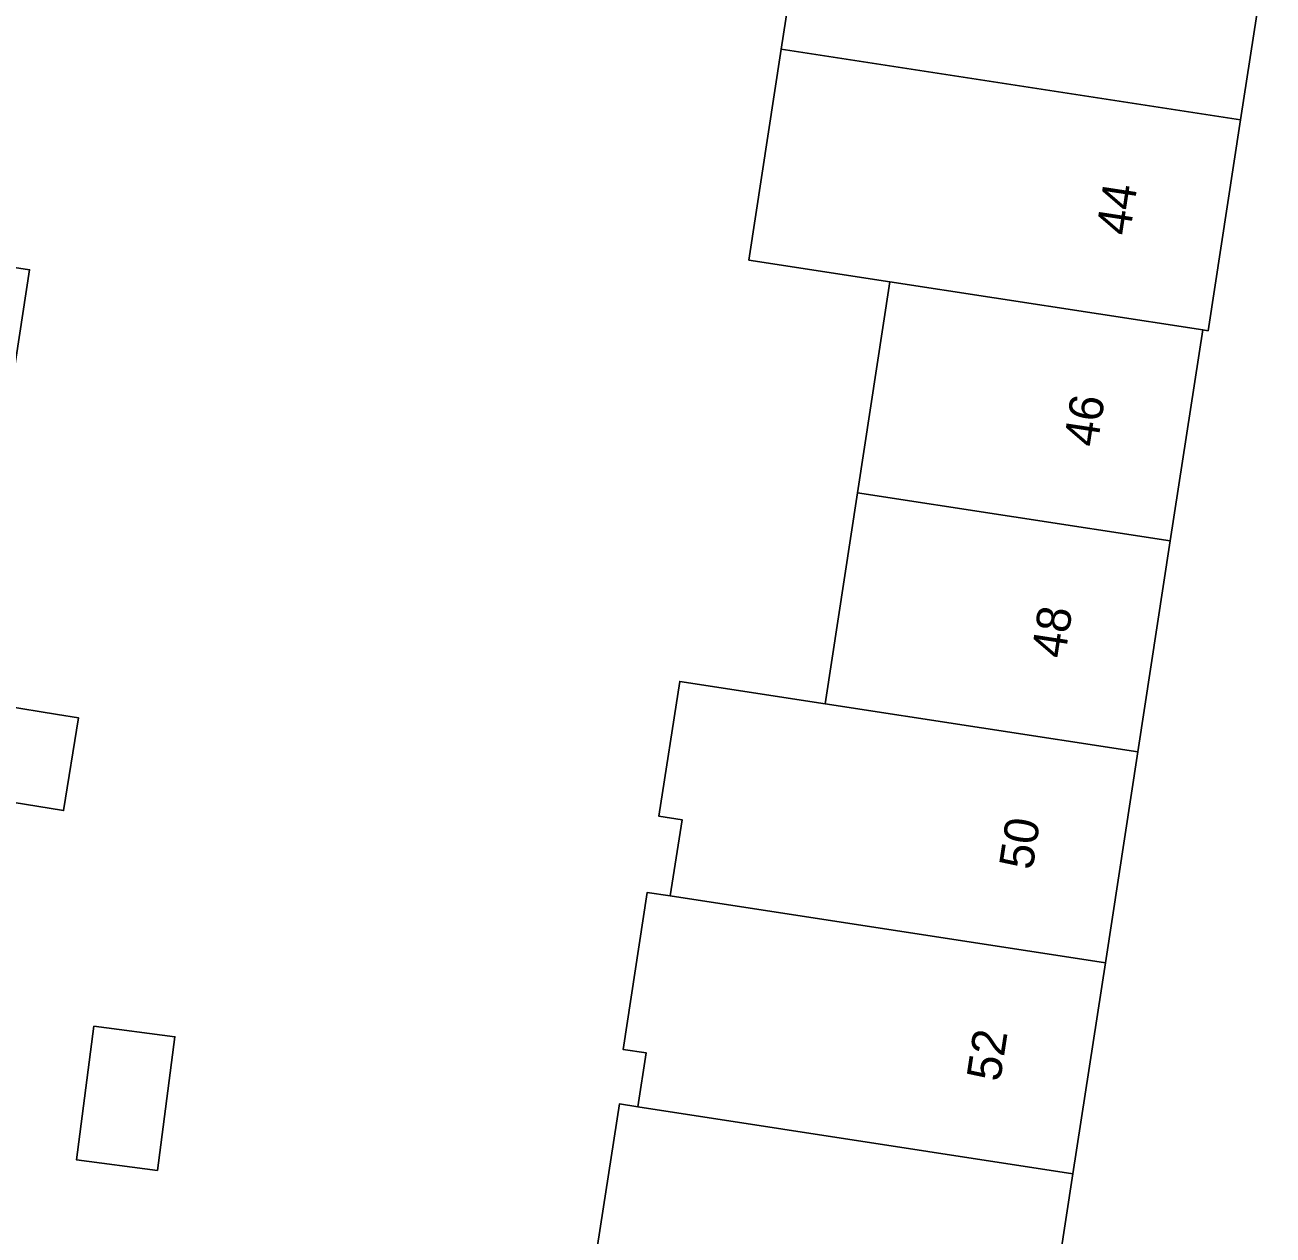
# Model space of a CAD drawing. Extents: x 161483 to 162250, y 379484 to 380833.
# Drawn here: x 162068.29 to 162104.92, y 380548.53 to 380584.05 of the extents above; entities that cross this region are included whole.
import ezdxf

# ---------------------------------------------------------------- set-up
doc = ezdxf.new("R2010")
doc.units = 0
for name, color, linetype in [('IMGEO_Erf', 7, 'Continuous'), ('IMGEO_Pand', 7, 'Continuous'), ('IMGEO_Pand_nummerreeks', 7, 'Continuous')]:
    doc.layers.add(name, color=color, linetype=linetype)

msp = doc.modelspace()

# ---------------------------------------------------------------- linework, layer by layer
at = {"layer": 'IMGEO_Erf'}
for points in [[(162104.903, 380587.33), (162103.971, 380581.267), (162103.018, 380575.074), (162102.86, 380575.098), (162101.908, 380568.906), (162100.956, 380562.714), (162100.003, 380556.522), (162099.051, 380550.33), (162098.099, 380544.138), (162097.119, 380537.766), (162083.147, 380539.987), (162082.606, 380536.471), (162081.595, 380528.392), (162091.517, 380526.858), (162101.213, 380525.474)], [(162093.677, 380576.511), (162089.537, 380577.148), (162090.489, 380583.341), (162091.032, 380586.872)], [(162085.098, 380548.228), (162085.736, 380552.379), (162086.279, 380552.295), (162086.523, 380553.879), (162085.846, 380553.983), (162086.555, 380558.591), (162087.231, 380558.487), (162087.575, 380560.721), (162086.898, 380560.825), (162087.507, 380564.783), (162091.772, 380564.127), (162092.724, 380570.319), (162093.677, 380576.511)], [(162067.691, 380564.063), (162069.245, 380563.811), (162069.863, 380563.711), (162069.423, 380560.992), (162064.586, 380561.774)]]:
    msp.add_lwpolyline(points, dxfattribs=at)
for points in [[(162067.637, 380571.741), (162062.833, 380572.48), (162063.227, 380575.041), (162063.622, 380577.602), (162068.425, 380576.862), (162068.031, 380574.302)], [(162070.314, 380554.665), (162072.69, 380554.352), (162072.174, 380550.429), (162069.797, 380550.741)]]:
    msp.add_lwpolyline(points, close=True, dxfattribs=at)
at = {"layer": 'IMGEO_Pand'}
for points in [[(162104.903, 380587.33), (162104.923, 380587.459), (162104.721, 380587.49), (162095.581, 380588.896), (162091.962, 380589.453), (162091.552, 380586.792), (162091.032, 380586.872), (162090.489, 380583.341), (162103.971, 380581.267)], [(162103.971, 380581.267), (162090.489, 380583.341), (162089.537, 380577.148), (162093.677, 380576.511), (162102.86, 380575.098), (162103.018, 380575.074)], [(162063.227, 380575.041), (162068.031, 380574.302), (162068.425, 380576.862), (162063.622, 380577.602)], [(162102.86, 380575.098), (162093.677, 380576.511), (162092.724, 380570.319), (162101.908, 380568.906)], [(162091.772, 380564.127), (162100.956, 380562.714), (162101.908, 380568.906), (162092.724, 380570.319)], [(162067.691, 380564.063), (162061.586, 380565.051), (162061.226, 380562.823), (162061.146, 380562.33), (162064.586, 380561.774), (162069.423, 380560.992), (162069.863, 380563.711), (162069.245, 380563.811)], [(162091.772, 380564.127), (162087.507, 380564.783), (162086.898, 380560.825), (162087.575, 380560.721), (162087.231, 380558.487), (162100.003, 380556.522), (162100.956, 380562.714)], [(162087.231, 380558.487), (162086.555, 380558.591), (162085.846, 380553.983), (162086.523, 380553.879), (162086.279, 380552.295), (162099.051, 380550.33), (162100.003, 380556.522)], [(162070.314, 380554.665), (162069.797, 380550.741), (162072.174, 380550.429), (162072.69, 380554.352)], [(162086.279, 380552.295), (162085.736, 380552.379), (162085.098, 380548.228), (162086.976, 380547.94), (162086.662, 380545.896), (162088.915, 380545.55), (162098.099, 380544.138), (162099.051, 380550.33)]]:
    msp.add_lwpolyline(points, close=True, dxfattribs=at)

# ---------------------------------------------------------------- texts
at = {"layer": 'IMGEO_Pand_nummerreeks'}
for s, rotation, p in [('44', 81.2855, (162100.714, 380577.84)), ('46', 81.2855, (162099.763, 380571.633)), ('48', 81.2882, (162098.812, 380565.429)), ('50', 81.2882, (162097.861, 380559.222)), ('52', 81.2882, (162096.909, 380553.009))]:
    msp.add_text(s, height=1, rotation=rotation, dxfattribs=at).set_placement(p)

doc.saveas('drawing.dxf')
